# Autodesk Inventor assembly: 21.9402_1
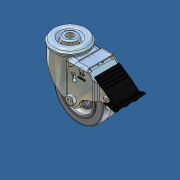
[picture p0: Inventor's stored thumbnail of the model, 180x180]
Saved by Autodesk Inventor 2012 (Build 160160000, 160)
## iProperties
Created: 2010-10
Part Number: 21.9402_1
Document SubType Name: Assembly
Designer: Administrator
Description: Caster 3.5" With Brake
Vendor: V
Mass: 727.273 g
Surface Area: 1132.62 cm^2
Volume: 236.976 cm^3
Density: 3.06898 g/cm^3
Translation Standard: STEP AP214IS
FileName: Colson-2.03256.445 BRK5 .step.step
PreProcessor: SolidWorks 2010
PostProcessor: Build: 236a, Release: 2009 RTM - Date: Fri 02/22/2008
Sent Units: Inches
Uncertainty: 1e-05
Title: Caster 3.5" With Brake
Author: Administrator
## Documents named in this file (9)
- C:\Andys Backup Data\ANDY'S INVENTOR\INVENTOR LIBRARIES\PARTS LIBRARY\FEET WHEELS FLOOR FASTENING SUPPORTS\SUBCOMPONENTS\21.9402_1 CASTER 3.5 BRK.iam
- C:\Andys Backup Data\ANDY'S INVENTOR\INVENTOR LIBRARIES\PARTS LIBRARY\FEET WHEELS FLOOR FASTENING SUPPORTS\SUBCOMPONENTS\21.9401 WHEEL FORK.ipt
- C:\Andys Backup Data\ANDY'S INVENTOR\INVENTOR LIBRARIES\PARTS LIBRARY\FEET WHEELS FLOOR FASTENING SUPPORTS\SUBCOMPONENTS\21.9401 LOWER RACEWAY.ipt
- C:\Andys Backup Data\ANDY'S INVENTOR\INVENTOR LIBRARIES\PARTS LIBRARY\FEET WHEELS FLOOR FASTENING SUPPORTS\SUBCOMPONENTS\21.9403 wheel assy.iam
- C:\Andys Backup Data\ANDY'S INVENTOR\INVENTOR LIBRARIES\PARTS LIBRARY\FEET WHEELS FLOOR FASTENING SUPPORTS\SUBCOMPONENTS\21.9401 WHEEL BOLT.ipt
- C:\Andys Backup Data\ANDY'S INVENTOR\INVENTOR LIBRARIES\PARTS LIBRARY\FEET WHEELS FLOOR FASTENING SUPPORTS\SUBCOMPONENTS\21.9401 WHEEL NUT.ipt
- C:\Andys Backup Data\ANDY'S INVENTOR\INVENTOR LIBRARIES\PARTS LIBRARY\FEET WHEELS FLOOR FASTENING SUPPORTS\SUBCOMPONENTS\21.9401 BRK_ASSY.iam
- C:\Andys Backup Data\ANDY'S INVENTOR\INVENTOR LIBRARIES\PARTS LIBRARY\FEET WHEELS FLOOR FASTENING SUPPORTS\SUBCOMPONENTS\21.9401 UPPER RACEWAY.ipt
- C:\Andys Backup Data\ANDY'S INVENTOR\INVENTOR LIBRARIES\PARTS LIBRARY\FEET WHEELS FLOOR FASTENING SUPPORTS\SUBCOMPONENTS\21.9402 MODULAR STEM.ipt
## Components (8 placed, 8 different names)
1. 21.9401 WHEEL FORK:1 — Mate:15, Mate:18
2. 21.9401 LOWER RACEWAY:1 — Mate:19, Mate:20
3. 21.9403 wheel assy:1 [sub-assembly] — Mate:10, Mate:22
4. 21.9401 WHEEL BOLT:1 — Mate:10, Mate:16, Mate:17, Mate:18
5. 21.9401 WHEEL NUT:1 — Insert:1, Angle:1
6. 21.9401 BRK_ASSY:1 [sub-assembly] — Mate:15, Mate:16, Mate:17, Insert:1, Angle:1
7. 21.9401 UPPER RACEWAY:1 — Mate:21
8. 21.9402 MODULAR STEM:1 — Mate:19, Mate:20, Mate:21, Mate:22
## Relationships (11: Mate 9, Insert 1, Angle 1)
- Mate:10: 21.9403 wheel assy:1 ↔ 21.9401 WHEEL BOLT:1
- Mate:15: 21.9401 WHEEL FORK:1 ↔ 21.9401 BRK_ASSY:1
- Mate:16: 21.9401 WHEEL BOLT:1 ↔ 21.9401 BRK_ASSY:1
- Mate:17: 21.9401 WHEEL BOLT:1 ↔ 21.9401 BRK_ASSY:1
- Mate:18: 21.9401 WHEEL FORK:1 ↔ 21.9401 WHEEL BOLT:1
- Mate:19: 21.9401 LOWER RACEWAY:1 ↔ 21.9402 MODULAR STEM:1
- Insert:1: 21.9401 WHEEL NUT:1 ↔ 21.9401 BRK_ASSY:1
- Angle:1: 21.9401 WHEEL NUT:1 ↔ 21.9401 BRK_ASSY:1
- Mate:20: 21.9401 LOWER RACEWAY:1 ↔ 21.9402 MODULAR STEM:1
- Mate:21: 21.9401 UPPER RACEWAY:1 ↔ 21.9402 MODULAR STEM:1
- Mate:22: 21.9403 wheel assy:1 ↔ 21.9402 MODULAR STEM:1
